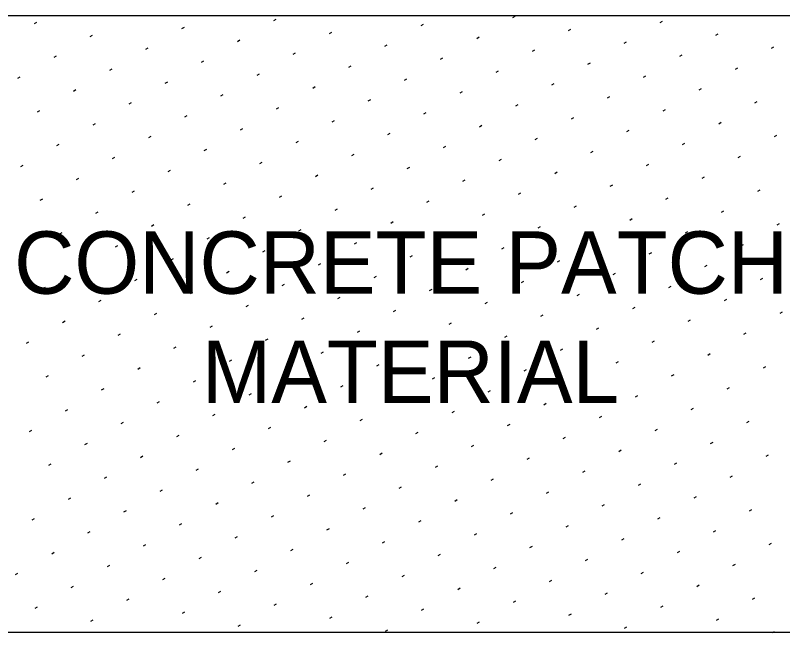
# Model space of a CAD drawing. Extents: x 49991.4 to 50021, y 49987.6 to 50011.4.
# Drawn here: x 50012.056 to 50013.04, y 49997.018 to 49997.81 of the extents above; entities that cross this region are included whole.
import ezdxf

# ---------------------------------------------------------------- set-up
doc = ezdxf.new("R2010")
doc.units = 0
for name, color, linetype in [('Level 1', 7, 'Continuous'), ('Level 2', 7, 'Continuous'), ('Level 3', 7, 'Continuous')]:
    doc.layers.add(name, color=color, linetype=linetype)

msp = doc.modelspace()

# ---------------------------------------------------------------- linework, layer by layer
at = {"layer": 'Level 1'}
for p, q in [((50002.45886, 49997.8102), (50013.61288, 49997.8102)), ((50013.61288, 49997.01828), (50002.45886, 49997.01828))]:
    msp.add_line(p, q, dxfattribs=at)
at = {"layer": 'Level 2'}
msp.add_line((50012.70837, 49997.35403), (50012.7114, 49997.35578), dxfattribs=at)
at = {"layer": 'Level 3'}
for p, q in [((50012.19802, 49997.80994), (50012.19848, 49997.8102)), ((50012.69373, 49997.80746), (50012.69676, 49997.80921)), ((50012.08034, 49997.79973), (50012.08337, 49997.80148)), ((50012.38703, 49997.80359), (50012.39007, 49997.80534)), ((50012.57605, 49997.79725), (50012.57908, 49997.799)), ((50012.88274, 49997.80112), (50012.88577, 49997.80287)), ((50012.26936, 49997.79339), (50012.27239, 49997.79514)), ((50012.45837, 49997.78705), (50012.4614, 49997.7888)), ((50012.76507, 49997.79091), (50012.7681, 49997.79266)), ((50012.15168, 49997.78318), (50012.15471, 49997.78493)), ((50012.3407, 49997.77684), (50012.34373, 49997.77859)), ((50012.64739, 49997.7807), (50012.65042, 49997.78245)), ((50012.95408, 49997.78457), (50012.95711, 49997.78632)), ((50012.22302, 49997.76664), (50012.22605, 49997.76839)), ((50012.52971, 49997.7705), (50012.53274, 49997.77225)), ((50012.8364, 49997.77436), (50012.83943, 49997.77611)), ((50013.02542, 49997.76802), (50013.02845, 49997.76977)), ((50012.10534, 49997.75643), (50012.10837, 49997.75818)), ((50012.41203, 49997.76029), (50012.41507, 49997.76204)), ((50012.71873, 49997.76416), (50012.72176, 49997.76591)), ((50012.90774, 49997.75781), (50012.91077, 49997.75956)), ((50012.29436, 49997.75009), (50012.29739, 49997.75184)), ((50012.60105, 49997.75395), (50012.60408, 49997.7557)), ((50012.79007, 49997.74761), (50012.7931, 49997.74936)), ((50012.17668, 49997.73988), (50012.17971, 49997.74163)), ((50012.48337, 49997.74375), (50012.4864, 49997.7455)), ((50012.67239, 49997.7374), (50012.67542, 49997.73915)), ((50012.97908, 49997.74127), (50012.98211, 49997.74302)), ((50012.059, 49997.72968), (50012.06204, 49997.73143)), ((50012.3657, 49997.73354), (50012.36873, 49997.73529)), ((50012.55471, 49997.7272), (50012.55774, 49997.72895)), ((50012.8614, 49997.73106), (50012.86443, 49997.73281)), ((50012.24802, 49997.72333), (50012.25105, 49997.72508)), ((50012.43703, 49997.71699), (50012.44007, 49997.71874)), ((50012.74373, 49997.72086), (50012.74676, 49997.72261)), ((50012.13034, 49997.71313), (50012.13337, 49997.71488)), ((50012.31936, 49997.70679), (50012.32239, 49997.70854)), ((50012.62605, 49997.71065), (50012.62908, 49997.7124)), ((50012.93274, 49997.71451), (50012.93577, 49997.71626)), ((50012.20168, 49997.69658), (50012.20471, 49997.69833)), ((50012.50837, 49997.70044), (50012.5114, 49997.70219)), ((50012.81507, 49997.70431), (50012.8181, 49997.70606)), ((50013.00408, 49997.69797), (50013.00711, 49997.69972)), ((50012.084, 49997.68637), (50012.08704, 49997.68812)), ((50012.3907, 49997.69024), (50012.39373, 49997.69199)), ((50012.69739, 49997.6941), (50012.70042, 49997.69585)), ((50012.8864, 49997.68776), (50012.88943, 49997.68951)), ((50012.27302, 49997.68003), (50012.27605, 49997.68178)), ((50012.57971, 49997.6839), (50012.58274, 49997.68565)), ((50012.76873, 49997.67755), (50012.77176, 49997.6793)), ((50012.15534, 49997.66983), (50012.15837, 49997.67158)), ((50012.46203, 49997.67369), (50012.46507, 49997.67544)), ((50012.65105, 49997.66735), (50012.65408, 49997.6691)), ((50012.95774, 49997.67121), (50012.96077, 49997.67296)), ((50012.34436, 49997.66349), (50012.34739, 49997.66524)), ((50012.53337, 49997.65714), (50012.5364, 49997.65889)), ((50012.84007, 49997.66101), (50012.8431, 49997.66276)), ((50012.22668, 49997.65328), (50012.22971, 49997.65503)), ((50012.72239, 49997.6508), (50012.72542, 49997.65255)), ((50013.02908, 49997.65466), (50013.03211, 49997.65641)), ((50012.109, 49997.64307), (50012.11204, 49997.64482)), ((50012.4157, 49997.64694), (50012.41873, 49997.64869)), ((50012.60471, 49997.6406), (50012.60774, 49997.64235)), ((50012.9114, 49997.64446), (50012.91443, 49997.64621)), ((50012.29802, 49997.63673), (50012.30105, 49997.63848)), ((50012.48703, 49997.63039), (50012.49007, 49997.63214)), ((50012.79373, 49997.63425), (50012.79676, 49997.636)), ((50012.98274, 49997.62791), (50012.98577, 49997.62966)), ((50012.18034, 49997.62653), (50012.18337, 49997.62828)), ((50012.36936, 49997.62018), (50012.37239, 49997.62193)), ((50012.67605, 49997.62405), (50012.67908, 49997.6258)), ((50012.86507, 49997.61771), (50012.8681, 49997.61946)), ((50012.06267, 49997.61632), (50012.0657, 49997.61807)), ((50012.25168, 49997.60998), (50012.25471, 49997.61173)), ((50012.55837, 49997.61384), (50012.5614, 49997.61559)), ((50012.134, 49997.59977), (50012.13704, 49997.60152)), ((50012.4407, 49997.60364), (50012.44373, 49997.60539)), ((50012.74739, 49997.6075), (50012.75042, 49997.60925)), ((50012.9364, 49997.60116), (50012.93943, 49997.60291)), ((50012.32302, 49997.59343), (50012.32605, 49997.59518)), ((50012.62971, 49997.59729), (50012.63274, 49997.59904)), ((50012.81873, 49997.59095), (50012.82176, 49997.5927)), ((50012.20534, 49997.58322), (50012.20837, 49997.58497)), ((50012.51203, 49997.58709), (50012.51507, 49997.58884)), ((50012.70105, 49997.58075), (50012.70408, 49997.5825)), ((50013.00774, 49997.58461), (50013.01077, 49997.58636)), ((50012.08767, 49997.57302), (50012.0907, 49997.57477)), ((50012.39436, 49997.57688), (50012.39739, 49997.57863)), ((50012.58337, 49997.57054), (50012.5864, 49997.57229)), ((50012.89007, 49997.5744), (50012.8931, 49997.57615)), ((50012.27668, 49997.56668), (50012.27971, 49997.56843)), ((50012.4657, 49997.56033), (50012.46873, 49997.56208)), ((50012.77239, 49997.5642), (50012.77542, 49997.56595)), ((50012.159, 49997.55647), (50012.16204, 49997.55822)), ((50012.34802, 49997.55013), (50012.35105, 49997.55188)), ((50012.65471, 49997.55399), (50012.65774, 49997.55574)), ((50012.9614, 49997.55786), (50012.96443, 49997.55961)), ((50012.23034, 49997.53992), (50012.23337, 49997.54167)), ((50012.53703, 49997.54379), (50012.54007, 49997.54554)), ((50012.84373, 49997.54765), (50012.84676, 49997.5494)), ((50013.03274, 49997.54131), (50013.03577, 49997.54306)), ((50012.11267, 49997.52972), (50012.1157, 49997.53147)), ((50012.41936, 49997.53358), (50012.42239, 49997.53533)), ((50012.72605, 49997.53744), (50012.72908, 49997.53919)), ((50012.91507, 49997.5311), (50012.9181, 49997.53285)), ((50012.30168, 49997.52338), (50012.30471, 49997.52513)), ((50012.60837, 49997.52724), (50012.6114, 49997.52899)), ((50012.79739, 49997.5209), (50012.80042, 49997.52265)), ((50012.184, 49997.51317), (50012.18704, 49997.51492)), ((50012.4907, 49997.51703), (50012.49373, 49997.51878)), ((50012.67971, 49997.51069), (50012.68274, 49997.51244)), ((50012.9864, 49997.51456), (50012.98943, 49997.51631)), ((50012.06633, 49997.50296), (50012.06936, 49997.50471)), ((50012.37302, 49997.50683), (50012.37605, 49997.50858)), ((50012.56203, 49997.50049), (50012.56507, 49997.50224)), ((50012.86873, 49997.50435), (50012.87176, 49997.5061)), ((50012.25534, 49997.49662), (50012.25837, 49997.49837)), ((50012.44436, 49997.49028), (50012.44739, 49997.49203)), ((50012.75105, 49997.49414), (50012.75408, 49997.49589)), ((50012.13767, 49997.48642), (50012.1407, 49997.48817)), ((50012.32668, 49997.48007), (50012.32971, 49997.48182)), ((50012.63337, 49997.48394), (50012.6364, 49997.48569)), ((50012.94007, 49997.4878), (50012.9431, 49997.48955)), ((50012.209, 49997.46987), (50012.21204, 49997.47162)), ((50012.5157, 49997.47373), (50012.51873, 49997.47548)), ((50012.82239, 49997.4776), (50012.82542, 49997.47935)), ((50013.0114, 49997.47125), (50013.01443, 49997.473)), ((50012.39802, 49997.46353), (50012.40105, 49997.46528)), ((50012.70471, 49997.46739), (50012.70774, 49997.46914)), ((50012.89373, 49997.46105), (50012.89676, 49997.4628)), ((50012.09133, 49997.45966), (50012.09436, 49997.46141)), ((50012.28034, 49997.45332), (50012.28337, 49997.45507)), ((50012.58703, 49997.45718), (50012.59007, 49997.45893)), ((50012.77605, 49997.45084), (50012.77908, 49997.45259)), ((50012.16267, 49997.44312), (50012.1657, 49997.44487)), ((50012.46936, 49997.44698), (50012.47239, 49997.44873)), ((50012.65837, 49997.44064), (50012.6614, 49997.44239)), ((50012.96507, 49997.4445), (50012.9681, 49997.44625)), ((50012.35168, 49997.43677), (50012.35471, 49997.43852)), ((50012.84739, 49997.43429), (50012.85042, 49997.43604)), ((50012.234, 49997.42657), (50012.23704, 49997.42832)), ((50012.5407, 49997.43043), (50012.54373, 49997.43218)), ((50012.72971, 49997.42409), (50012.73274, 49997.42584)), ((50013.0364, 49997.42795), (50013.03943, 49997.4297)), ((50012.11633, 49997.41636), (50012.11936, 49997.41811)), ((50012.42302, 49997.42023), (50012.42605, 49997.42198)), ((50012.61203, 49997.41388), (50012.61507, 49997.41563)), ((50012.91873, 49997.41775), (50012.92176, 49997.4195)), ((50012.30534, 49997.41002), (50012.30837, 49997.41177)), ((50012.49436, 49997.40368), (50012.49739, 49997.40543)), ((50012.80105, 49997.40754), (50012.80408, 49997.40929)), ((50012.99007, 49997.4012), (50012.9931, 49997.40295)), ((50012.18767, 49997.39981), (50012.1907, 49997.40156)), ((50012.37668, 49997.39347), (50012.37971, 49997.39522)), ((50012.68337, 49997.39734), (50012.6864, 49997.39909)), ((50012.06999, 49997.38961), (50012.07302, 49997.39136)), ((50012.259, 49997.38327), (50012.26204, 49997.38502)), ((50012.5657, 49997.38713), (50012.56873, 49997.38888)), ((50012.87239, 49997.39099), (50012.87542, 49997.39274)), ((50012.14133, 49997.37306), (50012.14436, 49997.37481)), ((50012.44802, 49997.37692), (50012.45105, 49997.37867)), ((50012.75471, 49997.38079), (50012.75774, 49997.38254)), ((50012.94373, 49997.37445), (50012.94676, 49997.3762)), ((50012.33034, 49997.36672), (50012.33337, 49997.36847)), ((50012.63703, 49997.37058), (50012.64007, 49997.37233)), ((50012.82605, 49997.36424), (50012.82908, 49997.36599)), ((50012.21267, 49997.35651), (50012.2157, 49997.35826)), ((50012.51936, 49997.36038), (50012.52239, 49997.36213)), ((50013.01507, 49997.3579), (50013.0181, 49997.35965)), ((50012.09499, 49997.34631), (50012.09802, 49997.34806)), ((50012.40168, 49997.35017), (50012.40471, 49997.35192)), ((50012.5907, 49997.34383), (50012.59373, 49997.34558)), ((50012.89739, 49997.34769), (50012.90042, 49997.34944)), ((50012.284, 49997.33996), (50012.28704, 49997.34171)), ((50012.47302, 49997.33362), (50012.47605, 49997.33537)), ((50012.77971, 49997.33749), (50012.78274, 49997.33924)), ((50012.16633, 49997.32976), (50012.16936, 49997.33151)), ((50012.35534, 49997.32342), (50012.35837, 49997.32517)), ((50012.66203, 49997.32728), (50012.66507, 49997.32903)), ((50012.96873, 49997.33114), (50012.97176, 49997.33289)), ((50012.23767, 49997.31321), (50012.2407, 49997.31496)), ((50012.54436, 49997.31707), (50012.54739, 49997.31882)), ((50012.85105, 49997.32094), (50012.85408, 49997.32269)), ((50012.11999, 49997.30301), (50012.12302, 49997.30476)), ((50012.42668, 49997.30687), (50012.42971, 49997.30862)), ((50012.73337, 49997.31073), (50012.7364, 49997.31248)), ((50012.92239, 49997.30439), (50012.92542, 49997.30614)), ((50012.309, 49997.29666), (50012.31204, 49997.29841)), ((50012.6157, 49997.30053), (50012.61873, 49997.30228)), ((50012.80471, 49997.29419), (50012.80774, 49997.29594)), ((50012.19133, 49997.28646), (50012.19436, 49997.28821)), ((50012.49802, 49997.29032), (50012.50105, 49997.29207)), ((50012.68703, 49997.28398), (50012.69007, 49997.28573)), ((50012.99373, 49997.28784), (50012.99676, 49997.28959)), ((50012.07365, 49997.27625), (50012.07668, 49997.278)), ((50012.38034, 49997.28012), (50012.38337, 49997.28187)), ((50012.56936, 49997.27377), (50012.57239, 49997.27552)), ((50012.87605, 49997.27764), (50012.87908, 49997.27939)), ((50012.26267, 49997.26991), (50012.2657, 49997.27166)), ((50012.45168, 49997.26357), (50012.45471, 49997.26532)), ((50012.75837, 49997.26743), (50012.7614, 49997.26918)), ((50012.14499, 49997.2597), (50012.14802, 49997.26145)), ((50012.334, 49997.25336), (50012.33704, 49997.25511)), ((50012.6407, 49997.25723), (50012.64373, 49997.25898)), ((50012.94739, 49997.26109), (50012.95042, 49997.26284)), ((50012.52302, 49997.24702), (50012.52605, 49997.24877)), ((50012.82971, 49997.25088), (50012.83274, 49997.25263)), ((50013.01873, 49997.24454), (50013.02176, 49997.24629)), ((50012.21633, 49997.24316), (50012.21936, 49997.24491)), ((50012.40534, 49997.23681), (50012.40837, 49997.23856)), ((50012.71203, 49997.24068), (50012.71507, 49997.24243)), ((50012.90105, 49997.23434), (50012.90408, 49997.23609)), ((50012.09865, 49997.23295), (50012.10168, 49997.2347)), ((50012.28767, 49997.22661), (50012.2907, 49997.22836)), ((50012.59436, 49997.23047), (50012.59739, 49997.23222)), ((50012.78337, 49997.22413), (50012.7864, 49997.22588)), ((50012.16999, 49997.2164), (50012.17302, 49997.21815)), ((50012.47668, 49997.22027), (50012.47971, 49997.22202)), ((50012.97239, 49997.21779), (50012.97542, 49997.21954)), ((50012.359, 49997.21006), (50012.36204, 49997.21181)), ((50012.6657, 49997.21392), (50012.66873, 49997.21567)), ((50012.85471, 49997.20758), (50012.85774, 49997.20933)), ((50012.24133, 49997.19986), (50012.24436, 49997.20161)), ((50012.54802, 49997.20372), (50012.55105, 49997.20547)), ((50012.73703, 49997.19738), (50012.74007, 49997.19913)), ((50012.12365, 49997.18965), (50012.12668, 49997.1914)), ((50012.43034, 49997.19351), (50012.43337, 49997.19526)), ((50012.61936, 49997.18717), (50012.62239, 49997.18892)), ((50012.92605, 49997.19103), (50012.92908, 49997.19278)), ((50012.31267, 49997.18331), (50012.3157, 49997.18506)), ((50012.50168, 49997.17697), (50012.50471, 49997.17872)), ((50012.80837, 49997.18083), (50012.8114, 49997.18258)), ((50012.19499, 49997.1731), (50012.19802, 49997.17485)), ((50012.384, 49997.16676), (50012.38704, 49997.16851)), ((50012.6907, 49997.17062), (50012.69373, 49997.17237)), ((50012.99739, 49997.17449), (50013.00042, 49997.17624)), ((50012.07731, 49997.1629), (50012.08034, 49997.16465)), ((50012.26633, 49997.15655), (50012.26936, 49997.1583)), ((50012.57302, 49997.16042), (50012.57605, 49997.16217)), ((50012.87971, 49997.16428), (50012.88274, 49997.16603)), ((50012.14865, 49997.14635), (50012.15168, 49997.1481)), ((50012.45534, 49997.15021), (50012.45837, 49997.15196)), ((50012.76203, 49997.15408), (50012.76507, 49997.15583)), ((50012.95105, 49997.14773), (50012.95408, 49997.14948)), ((50012.33767, 49997.14001), (50012.3407, 49997.14176)), ((50012.64436, 49997.14387), (50012.64739, 49997.14562)), ((50012.83337, 49997.13753), (50012.8364, 49997.13928)), ((50012.21999, 49997.1298), (50012.22302, 49997.13155)), ((50012.52668, 49997.13366), (50012.52971, 49997.13541)), ((50012.7157, 49997.12732), (50012.71873, 49997.12907)), ((50013.02239, 49997.13119), (50013.02542, 49997.13294)), ((50012.10231, 49997.11959), (50012.10534, 49997.12134)), ((50012.409, 49997.12346), (50012.41204, 49997.12521)), ((50012.59802, 49997.11712), (50012.60105, 49997.11887)), ((50012.90471, 49997.12098), (50012.90774, 49997.12273)), ((50012.29133, 49997.11325), (50012.29436, 49997.115)), ((50012.48034, 49997.10691), (50012.48337, 49997.10866)), ((50012.78703, 49997.11077), (50012.79007, 49997.11252)), ((50012.17365, 49997.10305), (50012.17668, 49997.1048)), ((50012.36267, 49997.0967), (50012.3657, 49997.09845)), ((50012.66936, 49997.10057), (50012.67239, 49997.10232)), ((50012.97605, 49997.10443), (50012.97908, 49997.10618)), ((50012.05597, 49997.09284), (50012.059, 49997.09459)), ((50012.24499, 49997.0865), (50012.24802, 49997.08825)), ((50012.55168, 49997.09036), (50012.55471, 49997.09211)), ((50012.85837, 49997.09423), (50012.8614, 49997.09598)), ((50012.12731, 49997.07629), (50012.13034, 49997.07804)), ((50012.434, 49997.08016), (50012.43704, 49997.08191)), ((50012.7407, 49997.08402), (50012.74373, 49997.08577)), ((50012.92971, 49997.07768), (50012.93274, 49997.07943)), ((50012.31633, 49997.06995), (50012.31936, 49997.0717)), ((50012.62302, 49997.07382), (50012.62605, 49997.07557)), ((50012.81203, 49997.06747), (50012.81507, 49997.06922)), ((50012.19865, 49997.05975), (50012.20168, 49997.0615)), ((50012.50534, 49997.06361), (50012.50837, 49997.06536)), ((50012.69436, 49997.05727), (50012.69739, 49997.05902)), ((50013.00105, 49997.06113), (50013.00408, 49997.06288)), ((50012.08097, 49997.04954), (50012.084, 49997.05129)), ((50012.38767, 49997.0534), (50012.3907, 49997.05515)), ((50012.57668, 49997.04706), (50012.57971, 49997.04881)), ((50012.88337, 49997.05093), (50012.8864, 49997.05268)), ((50012.26999, 49997.0432), (50012.27302, 49997.04495)), ((50012.459, 49997.03686), (50012.46204, 49997.03861)), ((50012.7657, 49997.04072), (50012.76873, 49997.04247)), ((50012.15231, 49997.03299), (50012.15534, 49997.03474)), ((50012.64802, 49997.03051), (50012.65105, 49997.03226)), ((50012.95471, 49997.03438), (50012.95774, 49997.03613)), ((50012.34133, 49997.02665), (50012.34436, 49997.0284)), ((50012.53034, 49997.02031), (50012.53337, 49997.02206)), ((50012.83703, 49997.02417), (50012.84007, 49997.02592)), ((50013.02682, 49997.01828), (50013.02908, 49997.01958))]:
    msp.add_line(p, q, dxfattribs=at)

# ---------------------------------------------------------------- texts
at = {"layer": 'Level 2'}
for s, p in [('CONCRETE PATCH', (50012.05411, 49997.45304)), ('MATERIAL', (50012.29482, 49997.31304))]:
    msp.add_text(s, height=0.08, dxfattribs=at).set_placement(p)

doc.saveas('drawing.dxf')
